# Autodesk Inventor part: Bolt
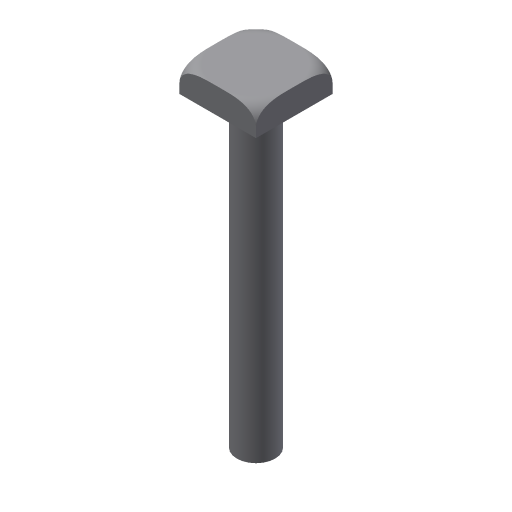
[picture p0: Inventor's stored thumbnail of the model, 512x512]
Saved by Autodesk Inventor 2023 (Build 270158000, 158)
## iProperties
Created: 2009-04
Part Number: Bolt
Document SubType Name: Modeling
Designer: Sham
Density: 1 g/cm^3
Material: Generic
Appearance: Default
Mass: 15.4123 g
Surface Area: 54.8695 cm^2
Volume: 15.4123 cm^3
Author: Sham
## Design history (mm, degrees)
sketch "Sketch1"
  geometry: L1 (-12, 12)-(12, 12); L2 (12, 12)-(12, -12); L3 (12, -12)-(-12, -12); L4 (-12, -12)-(-12, 12); 1 further point
  constraints: 8 end point, 2 parallel, 2 perpendicular, 1 horizontal, 1 other
  dimensions: "d0" = 24 distance of L1.start L1.end; "d1" = 12 distance from line of L2 point (0, 0); "d2" = 12 distance from line of L1 point (0, 0)
extrude "Extrusion1" new body sketch "Sketch1" distance "d3" = 8; taper "d4" = 0 deg
sketch "Sketch2"
  geometry: C1 r 6 at (0, 0)
  constraints: 1 centre point
  dimensions: "d5" = 12 diameter of C1
extrude "Extrusion2" join sketch "Sketch2" distance "d6" = 96; taper "d7" = 0 deg
workpoint "Work Point1"
workplane "Work Plane1"
sketch "Sketch3"
  geometry: L1 (33.941, 5)-(33.941, 6); L2 (28.941, 0)-(28.405, 0); L3 (16.971, 125.007)-(16.971, -22.043) reference; A1 r 5 centre (28.941, 5) between (28.941, 0) and (33.941, 5); 1 further point
  constraints: 4 end point, 2 point on circle, 2 point on line, 2 tangent, 1 centre point, 1 perpendicular
  dimensions: "d10" = 5 radius of A1
revolve "Revolution1" sketch "Sketch3" stored, may be unused: angle "d12" = 90 deg
body "Solid1"
other parameters: "d11" = 90 deg
